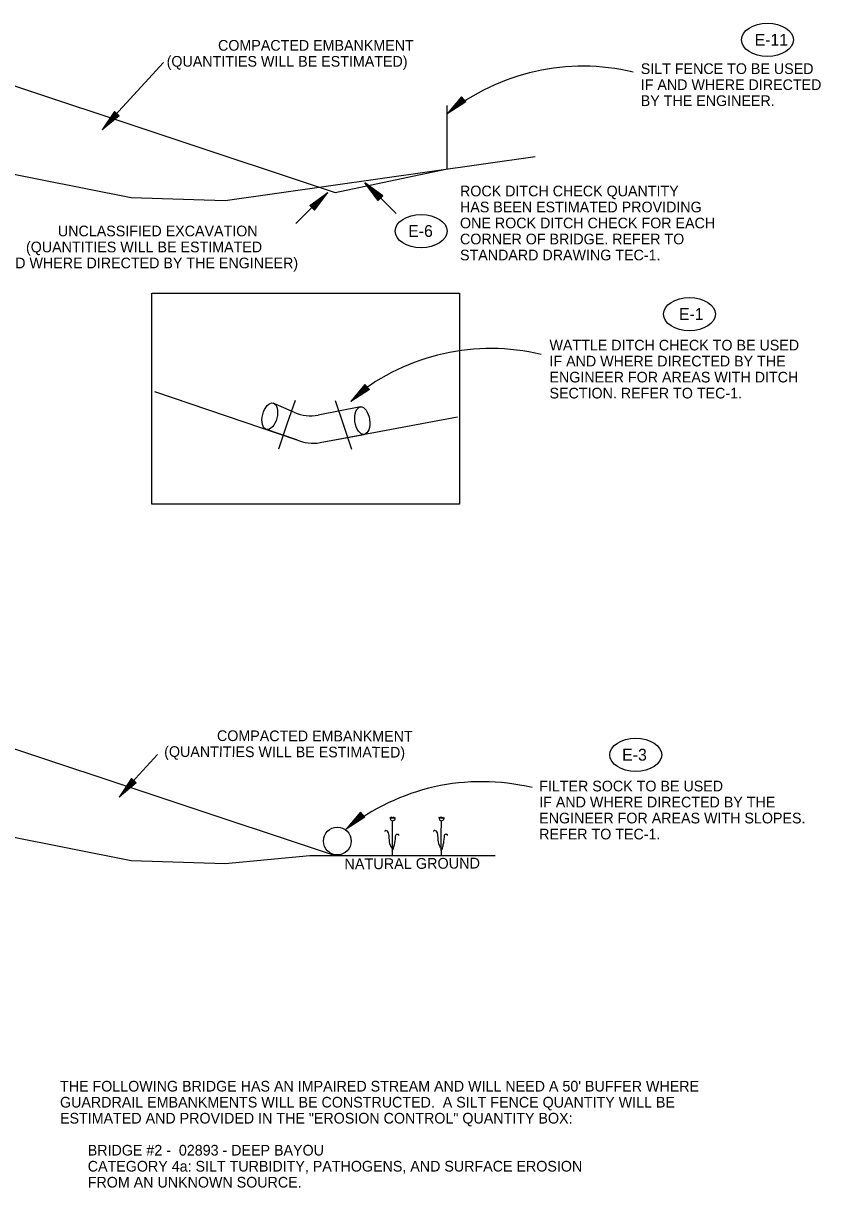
# Model space of a CAD drawing. Extents: x 1929624 to 1932607, y 596315 to 605533.
# Drawn here: x 1931112 to 1931560, y 604794 to 605448 of the extents above; entities that cross this region are included whole.
import ezdxf

# ---------------------------------------------------------------- set-up
doc = ezdxf.new("R2010")
doc.units = 0
for name, color, linetype in [('Default', 7, 'Continuous'), ('R_Border', 7, 'Continuous'), ('R_Draft', 7, 'Continuous')]:
    doc.layers.add(name, color=color, linetype=linetype)

msp = doc.modelspace()

# ---------------------------------------------------------------- linework, layer by layer
at = {"layer": 'Default'}
for p, q in [((1931052.26, 605431.37), (1931287.27, 605353.24)), ((1931190.75, 605426.41), (1931157.25, 605389.86)), ((1931358.35, 605407.12), (1931350.37, 605397.54)), ((1931360.83, 605404.34), (1931350.37, 605397.54)), ((1931358.58, 605406.86), (1931351.93, 605398.89)), ((1931360.61, 605404.57), (1931351.93, 605398.89)), ((1931358.78, 605406.63), (1931353.49, 605400.32)), ((1931360.38, 605404.8), (1931353.49, 605400.32)), ((1931358.97, 605406.42), (1931355.02, 605401.69)), ((1931360.19, 605405.01), (1931355.02, 605401.69)), ((1931359.18, 605406.16), (1931356.57, 605403.06)), ((1931359.99, 605405.25), (1931356.57, 605403.06)), ((1931359.4, 605405.93), (1931358.15, 605404.44)), ((1931359.79, 605405.51), (1931358.15, 605404.44)), ((1931360.83, 605404.34), (1931358.35, 605407.12)), ((1931163.13, 605398.8), (1931156.22, 605388.43)), ((1931165.84, 605396.34), (1931156.22, 605388.43)), ((1931163.38, 605398.61), (1931157.6, 605389.93)), ((1931165.65, 605396.53), (1931157.6, 605389.93)), ((1931163.64, 605398.37), (1931159.06, 605391.58)), ((1931165.37, 605396.75), (1931159.06, 605391.58)), ((1931163.81, 605398.15), (1931160.43, 605393.08)), ((1931165.14, 605396.96), (1931160.43, 605393.08)), ((1931164.04, 605397.98), (1931161.79, 605394.6)), ((1931164.89, 605397.18), (1931161.79, 605394.6)), ((1931165.84, 605396.34), (1931163.13, 605398.8)), ((1931164.27, 605397.75), (1931163.19, 605396.14)), ((1931164.71, 605397.43), (1931163.19, 605396.14)), ((1931287.27, 605353.24), (1931348.62, 605366.31)), ((1931311.57, 605348.78), (1931304.07, 605358.73)), ((1931314.13, 605351.38), (1931304.07, 605358.73)), ((1931321.62, 605341.52), (1931305.45, 605357.63)), ((1931311.76, 605348.97), (1931305.51, 605357.29)), ((1931313.94, 605351.15), (1931305.51, 605357.29)), ((1931313.68, 605350.9), (1931307.09, 605355.75)), ((1931311.99, 605349.23), (1931307.09, 605355.75)), ((1931265.24, 605335.85), (1931281.41, 605351.96)), ((1931273.05, 605345.99), (1931283.12, 605353.34)), ((1931273.25, 605345.76), (1931281.67, 605351.9)), ((1931273.5, 605345.51), (1931280.1, 605350.36)), ((1931275.19, 605343.84), (1931280.1, 605350.36)), ((1931275.42, 605343.58), (1931281.67, 605351.9)), ((1931275.62, 605343.39), (1931283.12, 605353.34)), ((1931312.22, 605349.45), (1931308.53, 605354.33)), ((1931313.45, 605350.73), (1931308.53, 605354.33)), ((1931313.28, 605350.51), (1931310, 605352.9)), ((1931312.45, 605349.69), (1931310, 605352.9)), ((1931313.04, 605350.29), (1931311.48, 605351.44)), ((1931312.7, 605349.86), (1931311.48, 605351.44)), ((1931311.57, 605348.78), (1931314.13, 605351.38)), ((1931275.62, 605343.39), (1931273.05, 605345.99)), ((1931273.73, 605345.34), (1931278.65, 605348.94)), ((1931273.91, 605345.12), (1931277.19, 605347.51)), ((1931274.14, 605344.9), (1931275.71, 605346.05)), ((1931274.49, 605344.48), (1931275.71, 605346.05)), ((1931274.74, 605344.3), (1931277.19, 605347.51)), ((1931274.97, 605344.06), (1931278.65, 605348.94)), ((1931304.07, 605245.27), (1931296.09, 605235.69)), ((1931304.3, 605245.01), (1931297.65, 605237.04)), ((1931304.5, 605244.78), (1931299.22, 605238.47)), ((1931304.69, 605244.57), (1931300.74, 605239.84)), ((1931306.55, 605242.49), (1931304.07, 605245.27)), ((1931185.65, 605241.36), (1931265.69, 605214.22)), ((1931306.55, 605242.49), (1931296.09, 605235.69)), ((1931306.33, 605242.72), (1931297.65, 605237.04)), ((1931306.11, 605242.95), (1931299.22, 605238.47)), ((1931305.91, 605243.16), (1931300.74, 605239.84)), ((1931304.9, 605244.31), (1931302.29, 605241.21)), ((1931305.71, 605243.39), (1931302.29, 605241.21)), ((1931305.12, 605244.08), (1931303.87, 605242.59)), ((1931305.51, 605243.65), (1931303.87, 605242.59)), ((1931278.96, 605212.68), (1931356.18, 605227.04)), ((1931052.39, 605058.51), (1931287.4, 604980.38)), ((1931187.35, 605037.19), (1931166.8, 605014.77)), ((1931172.68, 605023.71), (1931165.77, 605013.34)), ((1931172.93, 605023.52), (1931167.14, 605014.85)), ((1931173.18, 605023.28), (1931168.61, 605016.49)), ((1931173.36, 605023.06), (1931169.97, 605017.99)), ((1931174.69, 605021.88), (1931169.97, 605017.99)), ((1931173.59, 605022.89), (1931171.34, 605019.51)), ((1931174.44, 605022.1), (1931171.34, 605019.51)), ((1931175.39, 605021.25), (1931172.68, 605023.71)), ((1931173.82, 605022.67), (1931172.74, 605021.06)), ((1931174.26, 605022.34), (1931172.74, 605021.06)), ((1931175.39, 605021.25), (1931165.77, 605013.34)), ((1931175.2, 605021.44), (1931167.14, 605014.85)), ((1931174.92, 605021.66), (1931168.61, 605016.49)), ((1931301.53, 605004.77), (1931293.55, 604995.19)), ((1931301.76, 605004.51), (1931295.11, 604996.54)), ((1931303.79, 605002.22), (1931295.11, 604996.54)), ((1931301.96, 605004.28), (1931296.67, 604997.97)), ((1931303.57, 605002.45), (1931296.67, 604997.97)), ((1931302.15, 605004.07), (1931298.2, 604999.34)), ((1931303.37, 605002.66), (1931298.2, 604999.34)), ((1931302.36, 605003.81), (1931299.75, 605000.71)), ((1931303.17, 605002.89), (1931299.75, 605000.71)), ((1931302.58, 605003.58), (1931301.33, 605002.09)), ((1931302.97, 605003.15), (1931301.33, 605002.09)), ((1931304.01, 605001.99), (1931301.53, 605004.77)), ((1931304.01, 605001.99), (1931293.55, 604995.19))]:
    msp.add_line(p, q, dxfattribs=at)
for centre in [(1931426.56, 605302.62), (1931374.81, 605143.85), (1931369.74, 604900.25)]:
    msp.add_arc(centre, 121.72, 76.50197, 128.75222, dxfattribs=at)
at = {"layer": 'R_Border'}
for p, q in [((1931350.33, 605366.61), (1931350.33, 605402.3)), ((1931264.42, 605229.64), (1931252.48, 605234.89)), ((1931301.51, 605232.72), (1931277.7, 605228.1)), ((1931265.69, 605214.22), (1931248.07, 605220.18)), ((1931278.96, 605212.68), (1931303.59, 605217.25))]:
    msp.add_line(p, q, dxfattribs=at)
for points in [[(1930830.08, 605440.25), (1931067.62, 605371.32), (1931172.51, 605350.45), (1931225.36, 605348.85), (1931399.81, 605373.56)], [(1931264.74, 605236.36), (1931260.18, 605222.92), (1931255.41, 605208.86)], [(1931287.25, 605236.36), (1931291.81, 605222.92), (1931296.58, 605208.86)], [(1930830.21, 605067.4), (1931067.75, 604998.46), (1931172.64, 604977.6), (1931225.49, 604976), (1931273.1, 604980.37), (1931377.3, 604980.38)]]:
    msp.add_lwpolyline(points, dxfattribs=at)
msp.add_lwpolyline([(1931184.2, 605296.65), (1931357.2, 605296.65), (1931357.2, 605177.95), (1931184.2, 605177.95)], close=True, dxfattribs=at)
msp.add_circle((1931288.49, 604988.56), 7.8, dxfattribs=at)
for centre in [(1931273.53, 605250.17), (1931274.79, 605234.75), (1931274.79, 605234.75)]:
    msp.add_arc(centre, 22.47, 246.07844, 280.68558, dxfattribs=at)
for centre, major_axis, ratio in [((1931530.51, 605439.11), (14.6, 0), 0.638788), ((1931335.68, 605331.58), (14.6, 0), 0.638788), ((1931486.62, 605284.87), (14.6, 0), 0.638788), ((1931250.55, 605227.44), (-1.93, -7.45), 0.531792), ((1931302.55, 605224.99), (1.04, -7.73), 0.531792), ((1931456.4, 605037.06), (14.6, 0), 0.638788)]:
    msp.add_ellipse(centre, major_axis=major_axis, ratio=ratio, dxfattribs=at)
at = {"layer": 'R_Draft'}
for points in [[(1931318.32, 605001.96), (1931318.3, 605002.01), (1931318.79, 605001.3), (1931319.37, 605002.11), (1931319.8, 605001.33), (1931320.23, 605002.11), (1931320.63, 605001.34), (1931321.05, 605001.85)], [(1931345.8, 605001.97), (1931345.78, 605002.02), (1931346.27, 605001.31), (1931346.85, 605002.12), (1931347.28, 605001.34), (1931347.71, 605002.12), (1931348.11, 605001.35), (1931348.53, 605001.86)]]:
    msp.add_lwpolyline(points, dxfattribs=at)
for centre in [(1931319.66, 605001.46), (1931347.14, 605001.47)]:
    msp.add_arc(centre, 1.46, 161.12874, 15.45876, dxfattribs=at)
for points in [[(1931319.48, 605000.14), (1931319.4, 604997.03), (1931319.4, 604980.33)], [(1931346.96, 605000.15), (1931346.88, 604997.04), (1931346.88, 604980.34)], [(1931319.4, 604984.31), (1931318.45, 604986.14), (1931317.73, 604990.35), (1931315.9, 604994.56), (1931315.35, 604994.4), (1931315.18, 604993.92)], [(1931319.4, 604983.12), (1931319.95, 604983.99), (1931320.67, 604986.54), (1931321.31, 604990.74), (1931321.86, 604992.51), (1931322.35, 604992.51), (1931322.89, 604992.18), (1931322.89, 604991.71)], [(1931346.88, 604984.32), (1931345.93, 604986.15), (1931345.22, 604990.36), (1931343.39, 604994.57), (1931342.83, 604994.41), (1931342.67, 604993.93)], [(1931346.88, 604983.13), (1931347.44, 604984), (1931348.16, 604986.55), (1931348.79, 604990.75), (1931349.34, 604992.52), (1931349.83, 604992.52), (1931350.38, 604992.19), (1931350.38, 604991.72)]]:
    msp.add_spline(points, degree=3, dxfattribs=at)

# ---------------------------------------------------------------- texts
at = {"layer": 'Default'}
for s, p in [(' COMPACTED EMBANKMENT', (1931219.2, 605433.04)), ('(QUANTITIES WILL BE ESTIMATED)', (1931192.52, 605424.04)), ('SILT FENCE TO BE USED ', (1931459.23, 605419.92)), ('IF AND WHERE DIRECTED', (1931459.23, 605410.92)), ('BY THE ENGINEER. ', (1931459.23, 605401.92)), ('ROCK DITCH CHECK QUANTITY ', (1931357.55, 605351.13)), ('HAS BEEN ESTIMATED PROVIDING', (1931357.55, 605342.13)), ('ONE ROCK DITCH CHECK FOR EACH', (1931357.55, 605333.13)), ('UNCLASSIFIED EXCAVATION', (1931131.33, 605328.65)), ('CORNER OF BRIDGE. REFER TO', (1931357.55, 605324.13)), ('(QUANTITIES WILL BE ESTIMATED', (1931113.38, 605319.65)), ('IF AND WHERE DIRECTED BY THE ENGINEER)', (1931086.82, 605310.65)), ('STANDARD DRAWING TEC-1. ', (1931357.55, 605315.13)), ('WATTLE DITCH CHECK TO BE USED', (1931407.89, 605264.46)), ('IF AND WHERE DIRECTED BY THE', (1931407.89, 605255.46)), ('ENGINEER FOR AREAS WITH DITCH ', (1931407.89, 605246.46)), ('SECTION. REFER TO TEC-1.', (1931407.89, 605237.46)), ('FILTER SOCK TO BE USED', (1931402.1, 605016.5)), ('IF AND WHERE DIRECTED BY THE', (1931402.1, 605007.5)), ('ENGINEER FOR AREAS WITH SLOPES. ', (1931402.1, 604998.5)), ('REFER TO TEC-1.', (1931402.1, 604989.5))]:
    msp.add_text(s, height=6, dxfattribs=at).set_placement(p)
for s, height, rotation, p in [('COMPACTED EMBANKMENT', 6, 359.82713, (1931220.82, 605044.83)), ('(QUANTITIES WILL BE ESTIMATED)', 6, 359.82713, (1931191.12, 605035.92)), ('NATURAL GROUND', 6.075, 0.38559, (1931292.53, 604972.64))]:
    msp.add_text(s, height=height, rotation=rotation, dxfattribs=at).set_placement(p)
at = {"layer": 'R_Border'}
for s, p in [('E-11', (1931523.29, 605435.83)), ('E-6', (1931328.41, 605328.3)), ('E-1', (1931480.71, 605281.6)), ('E-3', (1931448.79, 605033.79))]:
    msp.add_text(s, height=6.663, rotation=360, dxfattribs=at).set_placement(p)
for s, p in [("THE FOLLOWING BRIDGE HAS AN IMPAIRED STREAM AND WILL NEED A 50' BUFFER WHERE", (1931132.52, 604847.72)), ('GUARDRAIL EMBANKMENTS WILL BE CONSTRUCTED.  A SILT FENCE QUANTITY WILL BE', (1931132.52, 604838.72)), ('ESTIMATED AND PROVIDED IN THE "EROSION CONTROL" QUANTITY BOX:', (1931132.52, 604829.72)), ('       BRIDGE #2 -  02893 - DEEP BAYOU', (1931132.52, 604811.72)), ('       CATEGORY 4a: SILT TURBIDITY, PATHOGENS, AND SURFACE EROSION ', (1931132.52, 604802.72)), ('       FROM AN UNKNOWN SOURCE.', (1931132.52, 604793.72))]:
    msp.add_text(s, height=6, dxfattribs=at).set_placement(p)

doc.saveas('drawing.dxf')
